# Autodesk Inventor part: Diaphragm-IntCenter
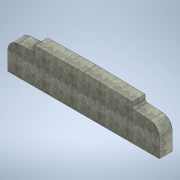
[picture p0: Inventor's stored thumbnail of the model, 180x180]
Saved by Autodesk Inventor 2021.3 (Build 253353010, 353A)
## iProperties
Created: 2021-10
Part Number: Diaphragm-IntCenter
Material: Concrete, Precast
Document SubType Name: Modeling
Designer: u1426
Density: 2.40731 g/cm^3
Appearance: Smooth Precast Structural
Author: u1426
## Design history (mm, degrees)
sketch "Sketch1"
  geometry: L1 (-762, 1295.4)-(-762, 1261.45); L2 (-726.164, 1223.417)-(-419.726, 1205.177); L3 (-228.6, 1002.336)-(-228.6, 635); L4 (-3225.8, 635)-(-3225.8, 1002.336); L5 (-2692.4, 1261.45)-(-2692.4, 1295.4); L6 (-2728.236, 1223.417)-(-3034.674, 1205.177); L7 (-3225.8, 635)-(-228.6, 635); L8 (-3302, 1295.4)-(-3302, 152.4); L9 (-152.4, 1295.4)-(-152.4, 152.4); L10 (-2692.4, 1295.4)-(-3302, 1295.4); L11 (-762, 1295.4)-(-152.4, 1295.4); L12 (-3302, 152.4)-(-4872.129, 152.4); L13 (-152.4, 152.4)-(-1248.139, 152.4); L14 (-2692.4, 1295.4)-(-2692.4, 1345.184); L15 (-762, 1345.184)-(-762, 1295.4); L16 (-2692.4, 1345.184)-(-1727.2, 1364.488); L17 (-1727.2, 1364.488)-(-762, 1345.184); A1 r 203.2 centre (-431.8, 1002.336) between (-228.6, 1002.336) and (-419.726, 1205.177); A2 r 38.1 centre (-723.9, 1261.45) between (-762, 1261.45) and (-726.164, 1223.417); A3 r 203.2 centre (-3022.6, 1002.336) between (-3034.674, 1205.177) and (-3225.8, 1002.336); A4 r 38.1 centre (-2730.5, 1261.45) between (-2728.236, 1223.417) and (-2692.4, 1261.45); 5 further points
  constraints: 34 end point, 8 point on circle, 8 point on line, 8 tangent, 5 vertical, 4 centre point, 2 horizontal, 2 perpendicular, 1 parallel
  dimensions: "d12" = 69.85 distance of L1.start point (-762, 1225.55); "d16" = 31.75 vertical distance of point (-762, 1225.55) point (-228.6, 1193.8); "d23" = 203.2 radius of A1; "d24" = 38.1 radius of A2; "d68" = 533.4 horizontal distance of point (-2692.4, 1225.55) point (-3225.8, 1193.8); "d69" = 31.75 vertical distance of point (-2692.4, 1225.55) point (-3225.8, 1193.8); "d70" = 69.85 distance of point (-2692.4, 1225.55) L5.end; "d78" = 203.2 radius of A3; "d79" = 38.1 radius of A4; "d82" = 76.2 distance between parallel lines of L3 L9; "d83" = 76.2 distance between parallel lines of L4 L8; "d84" = 1143 distance of L9.start L9.end; "d85" = 1143 distance of L8.start L8.end (= d84); "d86" = 482.6 distance from line of L4.start L12 (= d87); "d87" = 482.6 distance from line of L3.end L13; "d88" = 0 distance between parallel lines of L13 L12; "d89" = 3149.6 distance between parallel lines of L9 L8; "d90" = 49.784 distance of L5.end L14.end; "d91" = 152.4 distance from line of point (0, 0) L13; "d92" = 152.4 distance from line of point (0, 0) L9; "d93" = 533.4 distance between parallel lines of L3 L1; "d96" = 965.2 horizontal distance of L14.end L16.end; "d97" = 965.2 horizontal distance of L16.end L15.start (derived); "d98" = 19.304 vertical distance of L14.end L16.end (= 0.02 x d96); "d99" = 19.304 vertical distance of L16.end L15.start (= 0.02 x d97); "d100" = 49.784 distance of L15.start L1.start (derived)
extrude "Extrusion9" new body sketch "Sketch1" stored distance "d94" = 254; taper "d95" = 0 deg
body "Solid4"
